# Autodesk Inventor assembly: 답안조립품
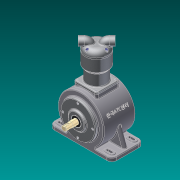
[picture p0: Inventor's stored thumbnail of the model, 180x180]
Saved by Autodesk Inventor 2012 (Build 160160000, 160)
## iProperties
Created: 2015-06
Part Number: 답안조립품
Document SubType Name: Assembly
Designer: Administrator
Author: Administrator
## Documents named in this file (15)
- C:\Users\Administrator\Desktop\450605V1028\답안조립품.iam
- C:\Users\Administrator\Desktop\450605V1028\본체.ipt
- C:\Users\Administrator\Desktop\450605V1028\메인커버.ipt
- C:\Users\Administrator\Desktop\450605V1028\M4x0.7.ipt
- C:\Users\Administrator\Desktop\450605V1028\실린더헤드.ipt
- C:\Users\Administrator\Desktop\450605V1028\실린더.ipt
- C:\Users\Administrator\Desktop\450605V1028\M5x0.8.ipt
- C:\Users\Administrator\Desktop\450605V1028\오일실.ipt
- C:\Users\Administrator\Desktop\450605V1028\베어링 6204.ipt
- C:\Users\Administrator\Desktop\450605V1028\메인 크랭크 축-구동부.ipt
- C:\Users\Administrator\Desktop\450605V1028\커넥팅 로드.ipt
- C:\Users\Administrator\Desktop\450605V1028\크랭크 서브축.ipt
- C:\Users\Administrator\Desktop\450605V1028\베어링 NA 4902.ipt
- C:\Users\Administrator\Desktop\450605V1028\피스톤 핀.ipt
- C:\Users\Administrator\Desktop\450605V1028\피스톤.ipt
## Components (14 placed, 4 different names)
1. M4x0.7:5
2. M4x0.7:6
3. M4x0.7:7
4. M4x0.7:8
5. M5x0.8:1
6. M5x0.8:2
7. M5x0.8:3
8. M5x0.8:4
9. 피스톤 핀:1 — 플러쉬:4
10. 피스톤:1
11. M4x0.7:1
12. M4x0.7:2
13. M4x0.7:3
14. M4x0.7:4
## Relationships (1: Flush 1)
- 플러쉬:4 [Flush]: 피스톤 핀:1
